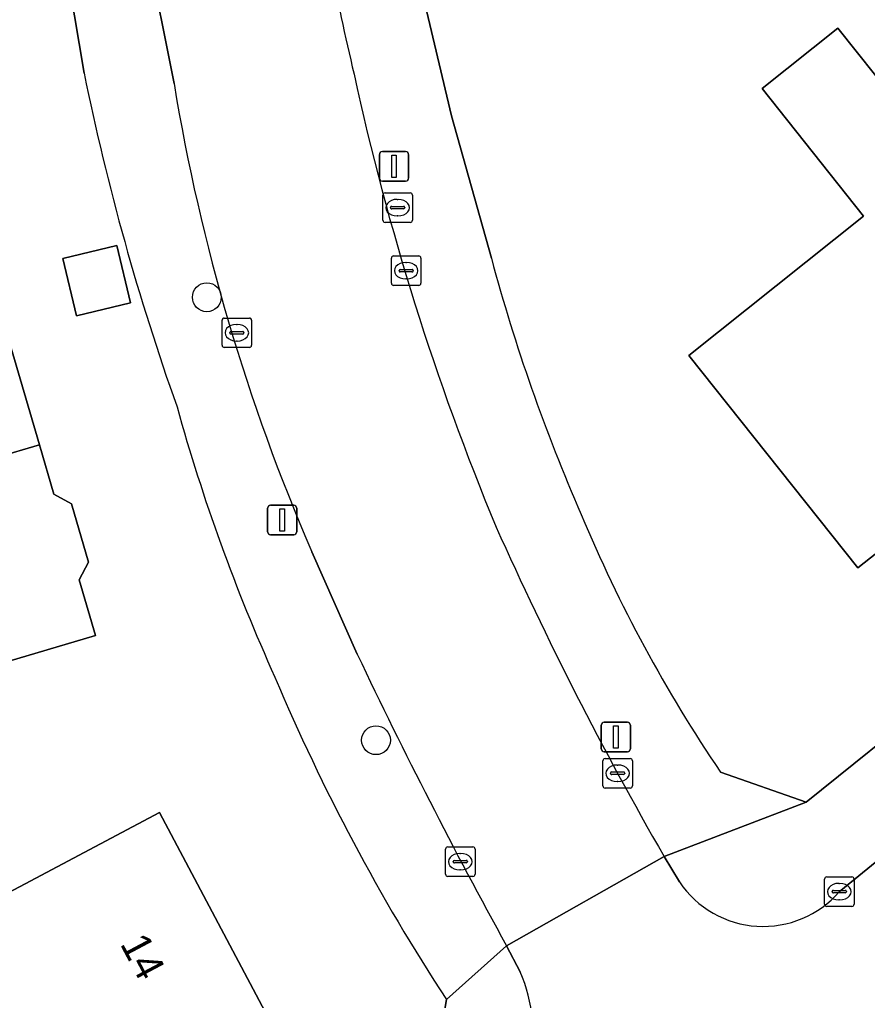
# Model space of a CAD drawing. Extents: x 161347 to 161881, y 382161 to 382804.
# Drawn here: x 161468.99 to 161497.74, y 382310.55 to 382343.81 of the extents above; entities that cross this region are included whole.
import ezdxf

# ---------------------------------------------------------------- set-up
doc = ezdxf.new("R2010")
doc.units = 0
for name, color, linetype in [('IMGEO_Boom', 7, 'Continuous'), ('IMGEO_Brandkraan', 7, 'Continuous'), ('IMGEO_Erf', 7, 'Continuous'), ('IMGEO_Kolk', 7, 'Continuous'), ('IMGEO_Lichtmast', 7, 'Continuous'), ('IMGEO_Pand', 7, 'Continuous'), ('IMGEO_Pand_nummerreeks', 7, 'Continuous'), ('IMGEO_Rijbaan_lokaal_open', 7, 'Continuous'), ('IMGEO_Voetpad_open', 7, 'Continuous')]:
    doc.layers.add(name, color=color, linetype=linetype)

msp = doc.modelspace()

# ---------------------------------------------------------------- linework, layer by layer
at = {"layer": 'IMGEO_Boom'}
for centre in [(161475.339, 382334.391), (161481.076, 382319.369)]:
    msp.add_circle(centre, 0.489, dxfattribs=at)
at = {"layer": 'IMGEO_Brandkraan'}
for p, q in [((161481.31, 382337.004), (161481.31, 382337.856)), ((161481.385, 382337.93), (161482.237, 382337.93)), ((161482.311, 382337.856), (161482.311, 382337.004)), ((161481.569, 382337.424), (161481.569, 382337.436)), ((161481.612, 382337.473), (161482.01, 382337.473)), ((161481.798, 382337.71), (161481.823, 382337.71)), ((161482.053, 382337.436), (161482.053, 382337.424)), ((161482.007, 382337.387), (161481.609, 382337.387)), ((161481.821, 382337.15), (161481.796, 382337.15)), ((161482.237, 382336.93), (161481.385, 382336.93))]:
    msp.add_line(p, q, dxfattribs=at)
for points in [[(161481.31, 382337.004), (161481.31, 382337.856)], [(161481.385, 382337.93), (161482.237, 382337.93)], [(161482.311, 382337.856), (161482.311, 382337.004)], [(161482.237, 382336.93), (161481.385, 382336.93)]]:
    msp.add_lwpolyline(points, dxfattribs=at)
for centre, radius, start, end in [((161481.387, 382337.854), 0.0765, 91.552, 178.448), ((161481.387, 382337.854), 0.0765, 91.552, 178.448), ((161482.235, 382337.854), 0.0765, 1.552, 88.448), ((161482.235, 382337.854), 0.0765, 1.552, 88.448), ((161481.609, 382337.433), 0.0403, 85.8775, 175.7526), ((161481.606, 382337.423), 0.0366, 178.938, 274.7102), ((161482.01, 382337.43), 0.043, 264.8664, 352.4533), ((161482.014, 382337.435), 0.0386, 1.7309, 96.639), ((161481.387, 382337.006), 0.0765, 181.552, 268.448), ((161481.387, 382337.006), 0.0765, 181.552, 268.448), ((161482.235, 382337.006), 0.0765, 271.552, 358.448), ((161482.235, 382337.006), 0.0765, 271.552, 358.448)]:
    msp.add_arc(centre, radius, start, end, dxfattribs=at)
for centre, major_axis, ratio, start_param, end_param in [((161481.797, 382337.43), (-0.387, 0.002), 0.722429, 4.712389, 7.853982), ((161481.822, 382337.43), (-0.39, 0.002), 0.717154, 1.570796, 4.712389)]:
    msp.add_ellipse(centre, major_axis=major_axis, ratio=ratio, start_param=start_param, end_param=end_param, dxfattribs=at)
at = {"layer": 'IMGEO_Erf'}
for points in [[(161492.761, 382318.284), (161495.67, 382317.265), (161500, 382320.746), (161506.91, 382326.302), (161519.365, 382335.787), (161532.97, 382344.41), (161567.929, 382365.979), (161578.374, 382372.283), (161617.144, 382396.335)], [(161471.178, 382341.99), (161470.024, 382348.841)], [(161482.485, 382345.416), (161483.643, 382340.539), (161484.991, 382335.711)], [(161467.896, 382335.364), (161469.662, 382329.389), (161470.156, 382327.712), (161470.747, 382327.391), (161471.332, 382325.408), (161471.006, 382324.807), (161471.563, 382322.92), (161461.712, 382320.009)], [(161430.356, 382262.72), (161462.576, 382290.867), (161473.855, 382299.824), (161482.817, 382306.734), (161483.463, 382310.577)]]:
    msp.add_lwpolyline(points, dxfattribs=at)
for points in [[(161511.691, 382336.608), (161508.532, 382334.091), (161508.385, 382332.789), (161507.808, 382332.33), (161506.507, 382332.477), (161505.918, 382332.008), (161502.662, 382329.412), (161502.518, 382328.135), (161501.894, 382327.638), (161500.663, 382327.777), (161500, 382327.253), (161497.42, 382325.215), (161491.686, 382332.42), (161497.616, 382337.139), (161494.169, 382341.47), (161496.735, 382343.512), (161498.649, 382341.115), (161498.885, 382341.304), (161499.745, 382341.991), (161500, 382342.195), (161502.125, 382343.894), (161502.363, 382343.594), (161504.663, 382345.427), (161508.575, 382340.519)], [(161472.289, 382336.141), (161472.751, 382334.201), (161470.916, 382333.764), (161470.454, 382335.705)], [(161473.729, 382316.918), (161477.514, 382309.794), (161477.004, 382309.524), (161477.33, 382308.911), (161474.644, 382307.484), (161474.333, 382308.07), (161469.531, 382305.518), (161468.703, 382307.077), (161467.82, 382306.608), (161465.09, 382311.746), (161455.881, 382306.854), (161453.078, 382312.13), (161458.706, 382314.316), (161466.527, 382317.259), (161468.254, 382314.009)]]:
    msp.add_lwpolyline(points, close=True, dxfattribs=at)
for centre, radius, start, end in [((161552.785, 382358.627), 83.286, 191.52291, 199.60785), ((161545.113, 382351.906), 62.265, 195.07589, 203.55705), ((161535.537, 382347.65), 63.517, 195.49792, 204.30672), ((161533.852, 382346.147), 49.647, 202.6588, 214.1404), ((161541.197, 382348.298), 68.964, 202.86139, 213.15888)]:
    msp.add_arc(centre, radius, start, end, dxfattribs=at)
at = {"layer": 'IMGEO_Kolk'}
for p, q in [((161481.674, 382335.792), (161482.526, 382335.792)), ((161481.599, 382334.866), (161481.599, 382335.718)), ((161482.087, 382335.572), (161482.112, 382335.572)), ((161482.6, 382335.718), (161482.6, 382334.866)), ((161481.858, 382335.286), (161481.858, 382335.298)), ((161482.296, 382335.249), (161481.898, 382335.249)), ((161481.901, 382335.335), (161482.299, 382335.335)), ((161482.342, 382335.298), (161482.342, 382335.286)), ((161482.526, 382334.792), (161481.674, 382334.792)), ((161482.11, 382335.012), (161482.085, 382335.012)), ((161475.857, 382332.761), (161475.857, 382333.613)), ((161475.932, 382333.687), (161476.784, 382333.687)), ((161476.345, 382333.467), (161476.37, 382333.467)), ((161476.858, 382333.613), (161476.858, 382332.761)), ((161476.116, 382333.181), (161476.116, 382333.193)), ((161476.554, 382333.144), (161476.156, 382333.144)), ((161476.159, 382333.23), (161476.557, 382333.23)), ((161476.6, 382333.193), (161476.6, 382333.181)), ((161476.368, 382332.907), (161476.343, 382332.907)), ((161476.784, 382332.687), (161475.932, 382332.687)), ((161488.771, 382317.823), (161488.771, 382318.675)), ((161488.846, 382318.749), (161489.698, 382318.749)), ((161489.259, 382318.529), (161489.284, 382318.529)), ((161489.772, 382318.675), (161489.772, 382317.823)), ((161489.03, 382318.243), (161489.03, 382318.255)), ((161489.468, 382318.206), (161489.07, 382318.206)), ((161489.073, 382318.292), (161489.471, 382318.292)), ((161489.514, 382318.255), (161489.514, 382318.243)), ((161489.282, 382317.969), (161489.257, 382317.969)), ((161489.698, 382317.749), (161488.846, 382317.749)), ((161483.435, 382314.825), (161483.435, 382315.677)), ((161483.51, 382315.751), (161484.362, 382315.751)), ((161483.923, 382315.531), (161483.948, 382315.531)), ((161484.436, 382315.677), (161484.436, 382314.825)), ((161483.694, 382315.245), (161483.694, 382315.257)), ((161484.132, 382315.208), (161483.734, 382315.208)), ((161483.737, 382315.294), (161484.135, 382315.294)), ((161484.178, 382315.257), (161484.178, 382315.245)), ((161483.946, 382314.971), (161483.921, 382314.971)), ((161484.362, 382314.751), (161483.51, 382314.751)), ((161496.289, 382313.809), (161496.289, 382314.661)), ((161496.364, 382314.735), (161497.216, 382314.735)), ((161496.777, 382314.515), (161496.802, 382314.515)), ((161497.29, 382314.661), (161497.29, 382313.809)), ((161496.548, 382314.229), (161496.548, 382314.241)), ((161496.986, 382314.192), (161496.588, 382314.192)), ((161496.591, 382314.278), (161496.989, 382314.278)), ((161497.032, 382314.241), (161497.032, 382314.229)), ((161496.8, 382313.955), (161496.775, 382313.955)), ((161497.216, 382313.735), (161496.364, 382313.735))]:
    msp.add_line(p, q, dxfattribs=at)
for points in [[(161481.674, 382335.792), (161482.526, 382335.792)], [(161481.599, 382334.866), (161481.599, 382335.718)], [(161482.6, 382335.718), (161482.6, 382334.866)], [(161482.526, 382334.792), (161481.674, 382334.792)], [(161475.857, 382332.761), (161475.857, 382333.613)], [(161475.932, 382333.687), (161476.784, 382333.687)], [(161476.858, 382333.613), (161476.858, 382332.761)], [(161476.784, 382332.687), (161475.932, 382332.687)], [(161488.771, 382317.823), (161488.771, 382318.675)], [(161488.846, 382318.749), (161489.698, 382318.749)], [(161489.772, 382318.675), (161489.772, 382317.823)], [(161489.698, 382317.749), (161488.846, 382317.749)], [(161483.435, 382314.825), (161483.435, 382315.677)], [(161483.51, 382315.751), (161484.362, 382315.751)], [(161484.436, 382315.677), (161484.436, 382314.825)], [(161484.362, 382314.751), (161483.51, 382314.751)], [(161496.289, 382313.809), (161496.289, 382314.661)], [(161496.364, 382314.735), (161497.216, 382314.735)], [(161497.29, 382314.661), (161497.29, 382313.809)], [(161497.216, 382313.735), (161496.364, 382313.735)]]:
    msp.add_lwpolyline(points, dxfattribs=at)
for centre, radius, start, end in [((161481.676, 382335.716), 0.0765, 91.552, 178.448), ((161481.676, 382335.716), 0.0765, 91.552, 178.448), ((161482.524, 382335.716), 0.0765, 1.552, 88.448), ((161482.524, 382335.716), 0.0765, 1.552, 88.448), ((161481.898, 382335.295), 0.0403, 85.8775, 175.7526), ((161481.895, 382335.285), 0.0366, 178.938, 274.7102), ((161482.299, 382335.292), 0.043, 264.8664, 352.4533), ((161482.303, 382335.297), 0.0386, 1.7309, 96.639), ((161481.676, 382334.868), 0.0765, 181.552, 268.448), ((161481.676, 382334.868), 0.0765, 181.552, 268.448), ((161482.524, 382334.868), 0.0765, 271.552, 358.448), ((161482.524, 382334.868), 0.0765, 271.552, 358.448), ((161475.934, 382333.611), 0.0765, 91.552, 178.448), ((161475.934, 382333.611), 0.0765, 91.552, 178.448), ((161476.782, 382333.611), 0.0765, 1.552, 88.448), ((161476.782, 382333.611), 0.0765, 1.552, 88.448), ((161476.156, 382333.19), 0.0403, 85.8775, 175.7526), ((161476.153, 382333.18), 0.0366, 178.938, 274.7102), ((161476.557, 382333.187), 0.043, 264.8664, 352.4533), ((161476.561, 382333.192), 0.0386, 1.7309, 96.639), ((161475.934, 382332.763), 0.0765, 181.552, 268.448), ((161475.934, 382332.763), 0.0765, 181.552, 268.448), ((161476.782, 382332.763), 0.0765, 271.552, 358.448), ((161476.782, 382332.763), 0.0765, 271.552, 358.448), ((161488.848, 382318.673), 0.0765, 91.552, 178.448), ((161488.848, 382318.673), 0.0765, 91.552, 178.448), ((161489.696, 382318.673), 0.0765, 1.552, 88.448), ((161489.696, 382318.673), 0.0765, 1.552, 88.448), ((161489.07, 382318.252), 0.0403, 85.8775, 175.7526), ((161489.067, 382318.242), 0.0366, 178.938, 274.7102), ((161489.471, 382318.249), 0.043, 264.8664, 352.4533), ((161489.475, 382318.254), 0.0386, 1.7309, 96.639), ((161488.848, 382317.825), 0.0765, 181.552, 268.448), ((161488.848, 382317.825), 0.0765, 181.552, 268.448), ((161489.696, 382317.825), 0.0765, 271.552, 358.448), ((161489.696, 382317.825), 0.0765, 271.552, 358.448), ((161483.512, 382315.675), 0.0765, 91.552, 178.448), ((161483.512, 382315.675), 0.0765, 91.552, 178.448), ((161484.36, 382315.675), 0.0765, 1.552, 88.448), ((161484.36, 382315.675), 0.0765, 1.552, 88.448), ((161483.734, 382315.254), 0.0403, 85.8775, 175.7526), ((161483.731, 382315.244), 0.0366, 178.938, 274.7102), ((161484.135, 382315.251), 0.043, 264.8664, 352.4533), ((161484.139, 382315.256), 0.0386, 1.7309, 96.639), ((161483.512, 382314.827), 0.0765, 181.552, 268.448), ((161483.512, 382314.827), 0.0765, 181.552, 268.448), ((161484.36, 382314.827), 0.0765, 271.552, 358.448), ((161484.36, 382314.827), 0.0765, 271.552, 358.448), ((161496.366, 382314.659), 0.0765, 91.552, 178.448), ((161496.366, 382314.659), 0.0765, 91.552, 178.448), ((161497.214, 382314.659), 0.0765, 1.552, 88.448), ((161497.214, 382314.659), 0.0765, 1.552, 88.448), ((161496.588, 382314.238), 0.0403, 85.8775, 175.7526), ((161496.585, 382314.228), 0.0366, 178.938, 274.7102), ((161496.989, 382314.235), 0.043, 264.8664, 352.4533), ((161496.993, 382314.24), 0.0386, 1.7309, 96.639), ((161496.366, 382313.811), 0.0765, 181.552, 268.448), ((161496.366, 382313.811), 0.0765, 181.552, 268.448), ((161497.214, 382313.811), 0.0765, 271.552, 358.448), ((161497.214, 382313.811), 0.0765, 271.552, 358.448)]:
    msp.add_arc(centre, radius, start, end, dxfattribs=at)
for centre, major_axis, ratio, start_param, end_param in [((161482.086, 382335.292), (-0.387, 0.002), 0.722429, 4.712389, 7.853982), ((161482.111, 382335.292), (-0.39, 0.002), 0.717154, 1.570796, 4.712389), ((161476.344, 382333.187), (-0.387, 0.002), 0.722429, 4.712389, 7.853982), ((161476.369, 382333.187), (-0.39, 0.002), 0.717154, 1.570796, 4.712389), ((161489.258, 382318.249), (-0.387, 0.002), 0.722429, 4.712389, 7.853982), ((161489.283, 382318.249), (-0.39, 0.002), 0.717154, 1.570796, 4.712389), ((161483.922, 382315.251), (-0.387, 0.002), 0.722429, 4.712389, 7.853982), ((161483.947, 382315.251), (-0.39, 0.002), 0.717154, 1.570796, 4.712389), ((161496.776, 382314.235), (-0.387, 0.002), 0.722429, 4.712389, 7.853982), ((161496.801, 382314.235), (-0.39, 0.002), 0.717154, 1.570796, 4.712389)]:
    msp.add_ellipse(centre, major_axis=major_axis, ratio=ratio, start_param=start_param, end_param=end_param, dxfattribs=at)
at = {"layer": 'IMGEO_Lichtmast'}
for p, q in [((161481.193, 382338.431), (161481.193, 382339.231)), ((161481.193, 382339.231), (161481.193, 382338.431)), ((161481.293, 382339.331), (161482.083, 382339.331)), ((161482.083, 382339.331), (161481.293, 382339.331)), ((161482.183, 382339.231), (161482.183, 382338.431)), ((161482.183, 382338.431), (161482.183, 382339.231)), ((161482.083, 382338.331), (161481.293, 382338.331)), ((161481.293, 382338.331), (161482.083, 382338.331)), ((161477.399, 382326.436), (161477.399, 382327.236)), ((161477.399, 382327.236), (161477.399, 382326.436)), ((161477.499, 382327.336), (161478.289, 382327.336)), ((161478.289, 382327.336), (161477.499, 382327.336)), ((161478.389, 382327.236), (161478.389, 382326.436)), ((161478.389, 382326.436), (161478.389, 382327.236)), ((161478.289, 382326.336), (161477.499, 382326.336)), ((161477.499, 382326.336), (161478.289, 382326.336)), ((161488.715, 382319.079), (161488.715, 382319.879)), ((161488.715, 382319.879), (161488.715, 382319.079)), ((161488.815, 382319.979), (161489.605, 382319.979)), ((161489.605, 382319.979), (161488.815, 382319.979)), ((161489.705, 382319.879), (161489.705, 382319.079)), ((161489.705, 382319.079), (161489.705, 382319.879)), ((161489.605, 382318.979), (161488.815, 382318.979)), ((161488.815, 382318.979), (161489.605, 382318.979))]:
    msp.add_line(p, q, dxfattribs=at)
for points in [[(161481.613, 382339.206), (161481.763, 382339.206), (161481.763, 382338.456), (161481.613, 382338.456), (161481.613, 382339.206)], [(161477.819, 382327.211), (161477.969, 382327.211), (161477.969, 382326.461), (161477.819, 382326.461), (161477.819, 382327.211)], [(161489.135, 382319.854), (161489.285, 382319.854), (161489.285, 382319.104), (161489.135, 382319.104), (161489.135, 382319.854)]]:
    msp.add_lwpolyline(points, dxfattribs=at)
for centre, start, end in [((161481.293, 382339.231), 90, 180), ((161481.293, 382339.231), 90, 180), ((161482.083, 382339.231), 0, 90), ((161482.083, 382339.231), 360, 90), ((161481.293, 382338.431), 180, 270), ((161481.293, 382338.431), 180, 270), ((161482.083, 382338.431), 270, 0), ((161482.083, 382338.431), 270, 0), ((161477.499, 382327.236), 90, 180), ((161477.499, 382327.236), 90, 180), ((161478.289, 382327.236), 0, 90), ((161478.289, 382327.236), 360, 90), ((161477.499, 382326.436), 180, 270), ((161477.499, 382326.436), 180, 270), ((161478.289, 382326.436), 270, 0), ((161478.289, 382326.436), 270, 0), ((161488.815, 382319.879), 90, 180), ((161488.815, 382319.879), 90, 180), ((161489.605, 382319.879), 0, 90), ((161489.605, 382319.879), 360, 90), ((161488.815, 382319.079), 180, 270), ((161488.815, 382319.079), 180, 270), ((161489.605, 382319.079), 270, 0), ((161489.605, 382319.079), 270, 0)]:
    msp.add_arc(centre, 0.1, start, end, dxfattribs=at)
at = {"layer": 'IMGEO_Pand'}
for points in [[(161498.649, 382341.115), (161496.735, 382343.512), (161494.169, 382341.47), (161497.616, 382337.139), (161491.686, 382332.42), (161497.42, 382325.215), (161500, 382327.253), (161500.663, 382327.777), (161501.894, 382327.638), (161502.518, 382328.135), (161502.662, 382329.412), (161505.918, 382332.008), (161500, 382339.422)], [(161470.454, 382335.705), (161470.916, 382333.764), (161472.751, 382334.201), (161472.289, 382336.141)], [(161469.662, 382329.389), (161467.896, 382335.364), (161458.129, 382332.474), (161459.09, 382329.223), (161454.833, 382327.966), (161455.689, 382325.067), (161457.05, 382325.47), (161459.503, 382326.197), (161459.45, 382326.375)], [(161469.662, 382329.389), (161459.45, 382326.375), (161459.503, 382326.197), (161457.05, 382325.47), (161457.139, 382325.168), (161457.364, 382324.406), (161457.844, 382322.784), (161456.058, 382322.257), (161458.192, 382314.224), (161458.504, 382314.347), (161462.877, 382316.067), (161461.712, 382320.009), (161471.563, 382322.92), (161471.006, 382324.807), (161471.332, 382325.408), (161470.747, 382327.391), (161470.156, 382327.712)], [(161477.514, 382309.794), (161473.729, 382316.918), (161468.254, 382314.009), (161466.527, 382317.259), (161458.706, 382314.316), (161453.078, 382312.13), (161455.881, 382306.854), (161465.09, 382311.746), (161467.82, 382306.608), (161468.703, 382307.077), (161469.531, 382305.518), (161474.333, 382308.07), (161474.644, 382307.484), (161477.33, 382308.911), (161477.004, 382309.524)]]:
    msp.add_lwpolyline(points, close=True, dxfattribs=at)
at = {"layer": 'IMGEO_Rijbaan_lokaal_open'}
for points in [[(161472.846, 382349.505), (161473.315, 382346.221), (161474.229, 382341.636)], [(161478.903, 382325.758), (161480.444, 382322.283)], [(161499.321, 382308.693), (161500, 382309.233), (161506.513, 382314.414), (161502.8, 382319.05), (161500, 382316.808), (161498.551, 382315.66), (161496.788, 382314.232)], [(161491.37, 382314.562), (161490.849, 382315.425), (161485.505, 382312.399), (161485.969, 382311.517)], [(161485.505, 382312.399), (161490.849, 382315.425)]]:
    msp.add_lwpolyline(points, dxfattribs=at)
for centre, radius, start, end in [((161550.911, 382358.887), 72.581, 187.26923, 193.48629), ((161567.752, 382360.955), 89.46, 192.25868, 202.58858), ((161540.887, 382352.631), 67.559, 189.36653, 203.43912), ((161596.458, 382376.32), 121.907, 204.07382, 209.96796), ((161642.711, 382399.132), 179.545, 205.34217, 208.88632), ((161494.206, 382316.476), 3.421, 214.013, 319.0161), ((161480.946, 382309.36), 5.466, 348.0466, 23.2401)]:
    msp.add_arc(centre, radius, start, end, dxfattribs=at)
at = {"layer": 'IMGEO_Voetpad_open'}
for points in [[(161588.821, 382375.192), (161595.489, 382379.316), (161598.349, 382381.063), (161606.195, 382385.906), (161608.544, 382387.356), (161617.711, 382393.014), (161617.891, 382393.131), (161617.144, 382396.335), (161578.374, 382372.283), (161567.929, 382365.979), (161532.97, 382344.41), (161519.365, 382335.787), (161506.91, 382326.302), (161500, 382320.746), (161495.67, 382317.265), (161490.849, 382315.425), (161491.37, 382314.562)], [(161474.229, 382341.636), (161473.315, 382346.221), (161472.846, 382349.505)], [(161470.024, 382348.841), (161471.178, 382341.99)], [(161483.643, 382340.539), (161482.485, 382345.416)], [(161484.991, 382335.711), (161483.643, 382340.539)], [(161496.788, 382314.232), (161498.551, 382315.66), (161500, 382316.808), (161502.8, 382319.05), (161504.93, 382320.757), (161514.379, 382328.325), (161515.799, 382329.456)], [(161480.444, 382322.283), (161478.903, 382325.758)], [(161490.849, 382315.425), (161495.67, 382317.265), (161492.761, 382318.284)], [(161485.969, 382311.517), (161485.505, 382312.399), (161483.463, 382310.577), (161482.817, 382306.734), (161473.855, 382299.824), (161462.576, 382290.867), (161430.356, 382262.72)], [(161483.463, 382310.577), (161485.505, 382312.399)]]:
    msp.add_lwpolyline(points, dxfattribs=at)
for centre, radius, start, end in [((161550.911, 382358.887), 72.581, 187.26923, 193.48629), ((161552.785, 382358.627), 83.286, 191.52291, 199.60785), ((161567.752, 382360.955), 89.46, 192.25868, 202.58858), ((161540.887, 382352.631), 67.559, 189.36653, 203.43912), ((161545.113, 382351.906), 62.265, 195.07589, 203.55705), ((161535.537, 382347.65), 63.517, 195.49792, 204.30672), ((161533.852, 382346.147), 49.647, 202.6588, 214.1404), ((161596.458, 382376.32), 121.907, 204.07382, 209.96796), ((161642.711, 382399.132), 179.545, 205.34217, 208.88632), ((161541.197, 382348.298), 68.964, 202.86139, 213.15888), ((161494.206, 382316.476), 3.421, 214.013, 319.0161), ((161480.946, 382309.36), 5.466, 348.0466, 23.2401)]:
    msp.add_arc(centre, radius, start, end, dxfattribs=at)

# ---------------------------------------------------------------- texts
at = {"layer": 'IMGEO_Pand_nummerreeks'}
msp.add_text('14', height=1, rotation=297.983, dxfattribs=at).set_placement((161472.38, 382312.466))

doc.saveas('drawing.dxf')
